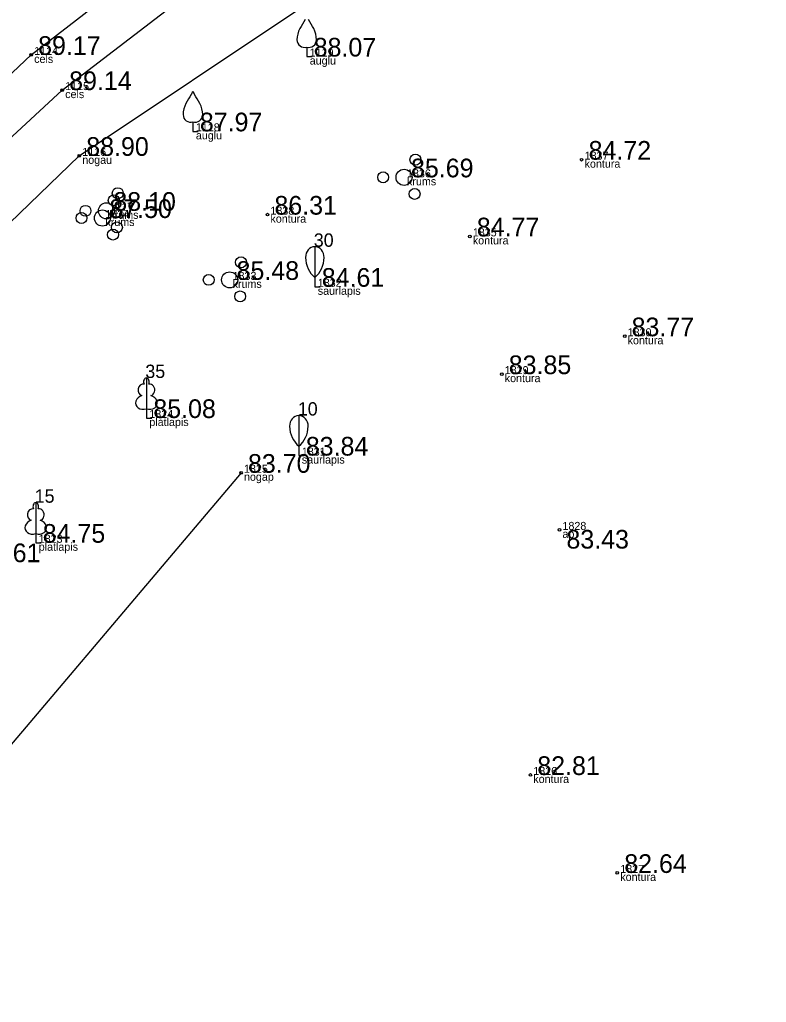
# Model space of a CAD drawing. Extents: x 614911 to 615803, y 262110 to 264311.
# Drawn here: x 615661.67 to 615689.65, y 263429.25 to 263466.07 of the extents above; entities that cross this region are included whole.
import ezdxf

# ---------------------------------------------------------------- set-up
doc = ezdxf.new("R2010")
doc.units = 0
for name, color, linetype in [('Level 1', 7, 'Continuous'), ('Level 31', 7, 'Continuous'), ('Level 37', 7, 'Continuous'), ('Level 53', 7, 'Continuous'), ('Level 54', 7, 'Continuous'), ('Level 57', 7, 'Continuous'), ('Level 58', 7, 'Continuous')]:
    doc.layers.add(name, color=color, linetype=linetype)

msp = doc.modelspace()

# ---------------------------------------------------------------- linework, layer by layer
at = {"layer": 'Level 1'}
for p, q in [((615672.428, 263465.044), (615672.428, 263464.692)), ((615672.428, 263464.692), (615672.628, 263464.692)), ((615668.163, 263462.241), (615668.163, 263461.889)), ((615668.163, 263461.889), (615668.363, 263461.889)), ((615672.731, 263456.417), (615672.731, 263456.065)), ((615672.731, 263456.065), (615672.931, 263456.065)), ((615666.42, 263451.495), (615666.42, 263451.148)), ((615666.42, 263451.148), (615666.62, 263451.148)), ((615672.133, 263450.092), (615672.133, 263449.74)), ((615672.133, 263449.74), (615672.333, 263449.74)), ((615662.275, 263446.821), (615662.275, 263446.474)), ((615662.275, 263446.474), (615662.475, 263446.474))]:
    msp.add_line(p, q, dxfattribs=at)
for points in [[(615672.731, 263457.565), (615672.731, 263456.417)], [(615666.42, 263452.648), (615666.42, 263451.495)], [(615666.51, 263452.416), (615666.509, 263452.417)], [(615672.133, 263451.24), (615672.133, 263450.092)], [(615662.275, 263447.974), (615662.275, 263446.821)], [(615662.365, 263447.742), (615662.364, 263447.743)]]:
    msp.add_lwpolyline(points, dxfattribs=at)
for centre, radius in [((615676.501, 263460.826), 0.207), ((615675.29, 263460.166), 0.204), ((615676.074, 263460.166), 0.301), ((615665.349, 263459.571), 0.207), ((615665.2, 263459.302), 0.207), ((615676.469, 263459.546), 0.205), ((615664.138, 263458.911), 0.204), ((615664.922, 263458.911), 0.301), ((615663.989, 263458.642), 0.204), ((615664.773, 263458.642), 0.301), ((615665.317, 263458.291), 0.205), ((615665.168, 263458.022), 0.205), ((615669.966, 263456.984), 0.207), ((615668.755, 263456.324), 0.204), ((615669.539, 263456.324), 0.301), ((615669.934, 263455.704), 0.205)]:
    msp.add_circle(centre, radius, dxfattribs=at)
for centre, radius, start, end in [((615685.053, 263458.296), 14.88, 148.4844, 149.9901), ((615659.803, 263458.296), 14.88, 30.0099, 31.5156), ((615672.952, 263465.317), 0.89, 151.757, 179.9138), ((615671.904, 263465.317), 0.89, 0.0862, 28.243), ((615672.352, 263465.323), 0.29, 181.0782, 285.2823), ((615672.504, 263465.323), 0.29, 254.7177, 358.9218), ((615680.788, 263455.493), 14.88, 148.4844, 149.9901), ((615667.746, 263463.527), 0.439, 324.3837, 341.712), ((615668.58, 263463.527), 0.439, 198.288, 215.6163), ((615655.538, 263455.493), 14.88, 30.0099, 31.5156), ((615668.687, 263462.514), 0.89, 151.757, 179.9138), ((615667.639, 263462.514), 0.89, 0.0862, 28.243), ((615668.087, 263462.52), 0.29, 181.0782, 285.2823), ((615668.239, 263462.52), 0.29, 254.7177, 358.9218)]:
    msp.add_arc(centre, radius, start, end, dxfattribs=at)
for centre, major_axis, ratio, start_param, end_param in [((615672.731, 263457.165), (0, 0.4), 0.875, 0, 1.570796), ((615672.731, 263457.165), (0, -0.4), 0.875, 1.570796, 3.141593), ((615673.206, 263457.188), (0, -0.943), 0.875, 4.7372, 5.669711), ((615672.256, 263457.188), (0, -0.943), 0.875, 0.613474, 1.545985), ((615666.292, 263452.203), (-0.039, -0.212), 0.861323, 3.141593, 6.283185), ((615666.42, 263452.498), (0, -0.15), 0.707107, 3.14537, 5.287485), ((615666.42, 263452.498), (0, -0.15), 0.707107, 0.995701, 3.137816), ((615666.548, 263452.203), (0.039, -0.212), 0.861323, 0, 3.141593), ((615666.33, 263451.741), (0.307, 0.095), 0.814445, 1.570796, 4.752015), ((615666.51, 263451.741), (-0.307, 0.095), 0.814445, 1.531171, 4.712389), ((615672.133, 263450.84), (0, 0.4), 0.875, 0, 1.570796), ((615672.133, 263450.84), (0, -0.4), 0.875, 1.570796, 3.141593), ((615672.608, 263450.863), (0, -0.943), 0.875, 4.7372, 5.669711), ((615671.658, 263450.863), (0, -0.943), 0.875, 0.613474, 1.545985), ((615662.147, 263447.529), (-0.039, -0.212), 0.861323, 3.141593, 6.283185), ((615662.275, 263447.824), (0, -0.15), 0.707107, 3.14537, 5.287485), ((615662.275, 263447.824), (0, -0.15), 0.707107, 0.995701, 3.137816), ((615662.403, 263447.529), (0.039, -0.212), 0.861323, 0, 3.141593), ((615662.185, 263447.067), (0.307, 0.095), 0.814445, 1.570796, 4.752015), ((615662.365, 263447.067), (-0.307, 0.095), 0.814445, 1.531171, 4.712389)]:
    msp.add_ellipse(centre, major_axis=major_axis, ratio=ratio, start_param=start_param, end_param=end_param, dxfattribs=at)
at = {"layer": 'Level 31'}
for points in [[(615645.025, 263435.572), (615644.689, 263438.503), (615649.02, 263446.598), (615663.907, 263460.971), (615672.355, 263466.622), (615674.709, 263468.018), (615689.528, 263477.228)], [(615669.966, 263449.096), (615658.187, 263435.178), (615653.795, 263425.523)]]:
    msp.add_lwpolyline(points, dxfattribs=at)
at = {"layer": 'Level 37'}
for points in [[(615640.593, 263444.077), (615645.77, 263448.925), (615656.412, 263459.375), (615662.104, 263464.753), (615672.019, 263472.421), (615683.77, 263481.412), (615685.947, 263482.698), (615692.438, 263486.438), (615704.553, 263493.789), (615734.729, 263515.331), (615744.043, 263521.815)], [(615642.494, 263442.163), (615647.437, 263447.751), (615657.328, 263457.944), (615663.266, 263463.435), (615673.138, 263471.007), (615685.255, 263480.126), (615686.777, 263481.148), (615694.593, 263485.712), (615707.185, 263493.203), (615735.25, 263513.819), (615744.602, 263520.653)]]:
    msp.add_lwpolyline(points, dxfattribs=at)
at = {"layer": 'Level 57'}
for centre in [(615662.104, 263464.753), (615663.266, 263463.435), (615663.907, 263460.971), (615682.728, 263460.827), (615670.957, 263458.768), (615678.54, 263457.953), (615684.34, 263454.211), (615679.736, 263452.792), (615669.966, 263449.096), (615681.898, 263446.956), (615680.806, 263437.773), (615684.065, 263434.103)]:
    msp.add_circle(centre, 0.05, dxfattribs=at)
at = {"layer": 'Level 58'}
for centre in [(615662.104, 263464.753), (615663.266, 263463.435), (615663.907, 263460.971), (615682.728, 263460.827), (615670.957, 263458.768), (615678.54, 263457.953), (615684.34, 263454.211), (615679.736, 263452.792), (615669.966, 263449.096), (615681.898, 263446.956), (615680.806, 263437.773), (615684.065, 263434.103)]:
    msp.add_circle(centre, 0.05, dxfattribs=at)

# ---------------------------------------------------------------- texts
at = {"layer": 'Level 1'}
for s, p in [(' 30', (615672.506, 263457.565)), (' 35', (615666.195, 263452.648)), (' 10', (615671.908, 263451.24)), (' 15', (615662.05, 263447.974))]:
    msp.add_text(s, height=0.5, dxfattribs=at).set_placement(p)
at = {"layer": 'Level 53'}
for s, p in [(' cels', (615662.104, 263464.453)), (' auglu', (615672.428, 263464.392)), (' cels', (615663.266, 263463.135)), (' auglu', (615668.163, 263461.589)), (' nogau', (615663.907, 263460.671)), (' kontura', (615682.728, 263460.527)), (' krums', (615676.074, 263459.866)), (' krums', (615664.773, 263458.342)), (' krums', (615664.922, 263458.611)), (' kontura', (615670.957, 263458.468)), (' kontura', (615678.54, 263457.653)), (' krums', (615669.539, 263456.024)), (' saurlapis', (615672.731, 263455.765)), (' kontura', (615684.34, 263453.911)), (' kontura', (615679.736, 263452.492)), (' platlapis', (615666.42, 263450.848)), (' saurlapis', (615672.133, 263449.44)), (' nogap', (615669.966, 263448.796)), (' ap', (615681.898, 263446.656)), (' platlapis', (615662.275, 263446.174)), (' kontura', (615680.806, 263437.473)), (' kontura', (615684.065, 263433.803))]:
    msp.add_text(s, height=0.3, dxfattribs=at).set_placement(p)
at = {"layer": 'Level 54'}
for s, p in [(' 1114', (615662.104, 263464.753)), (' 1119', (615672.428, 263464.692)), (' 1115', (615663.266, 263463.435)), (' 1118', (615668.163, 263461.889)), (' 1116', (615663.907, 263460.971)), (' 1837', (615682.728, 263460.827)), (' 1836', (615676.074, 263460.166)), (' 1117', (615664.922, 263458.911)), (' 1838', (615670.957, 263458.768)), (' 1834', (615664.773, 263458.642)), (' 1835', (615678.54, 263457.953)), (' 1833', (615669.539, 263456.324)), (' 1832', (615672.731, 263456.065)), (' 1830', (615684.34, 263454.211)), (' 1829', (615679.736, 263452.792)), (' 1824', (615666.42, 263451.148)), (' 1831', (615672.133, 263449.74)), (' 1825', (615669.966, 263449.096)), (' 1828', (615681.898, 263446.956)), (' 1823', (615662.275, 263446.474)), (' 1826', (615680.806, 263437.773)), (' 1827', (615684.065, 263434.103))]:
    msp.add_text(s, height=0.3, dxfattribs=at).set_placement(p)
at = {"layer": 'Level 58'}
for s, p in [(' 89.17', (615662.104, 263464.753)), (' 88.07', (615672.428, 263464.692)), (' 89.14', (615663.266, 263463.435)), (' 87.97', (615668.163, 263461.889)), (' 88.90', (615663.907, 263460.971)), (' 84.72', (615682.728, 263460.827)), (' 85.69', (615676.074, 263460.166)), (' 88.10', (615664.922, 263458.911)), (' 86.31', (615670.957, 263458.768)), (' 87.50', (615664.773, 263458.642)), (' 84.77', (615678.54, 263457.953)), (' 85.48', (615669.539, 263456.324)), (' 84.61', (615672.731, 263456.065)), (' 83.77', (615684.34, 263454.211)), (' 83.85', (615679.736, 263452.792)), (' 85.08', (615666.42, 263451.148)), (' 83.84', (615672.133, 263449.74)), (' 83.70', (615669.966, 263449.096)), (' 84.75', (615662.275, 263446.474)), (' 83.43', (615681.898, 263446.256)), (' 85.61', (615659.849, 263445.746)), (' 82.81', (615680.806, 263437.773)), (' 82.64', (615684.065, 263434.103))]:
    msp.add_text(s, height=0.7, dxfattribs=at).set_placement(p)

doc.saveas('drawing.dxf')
